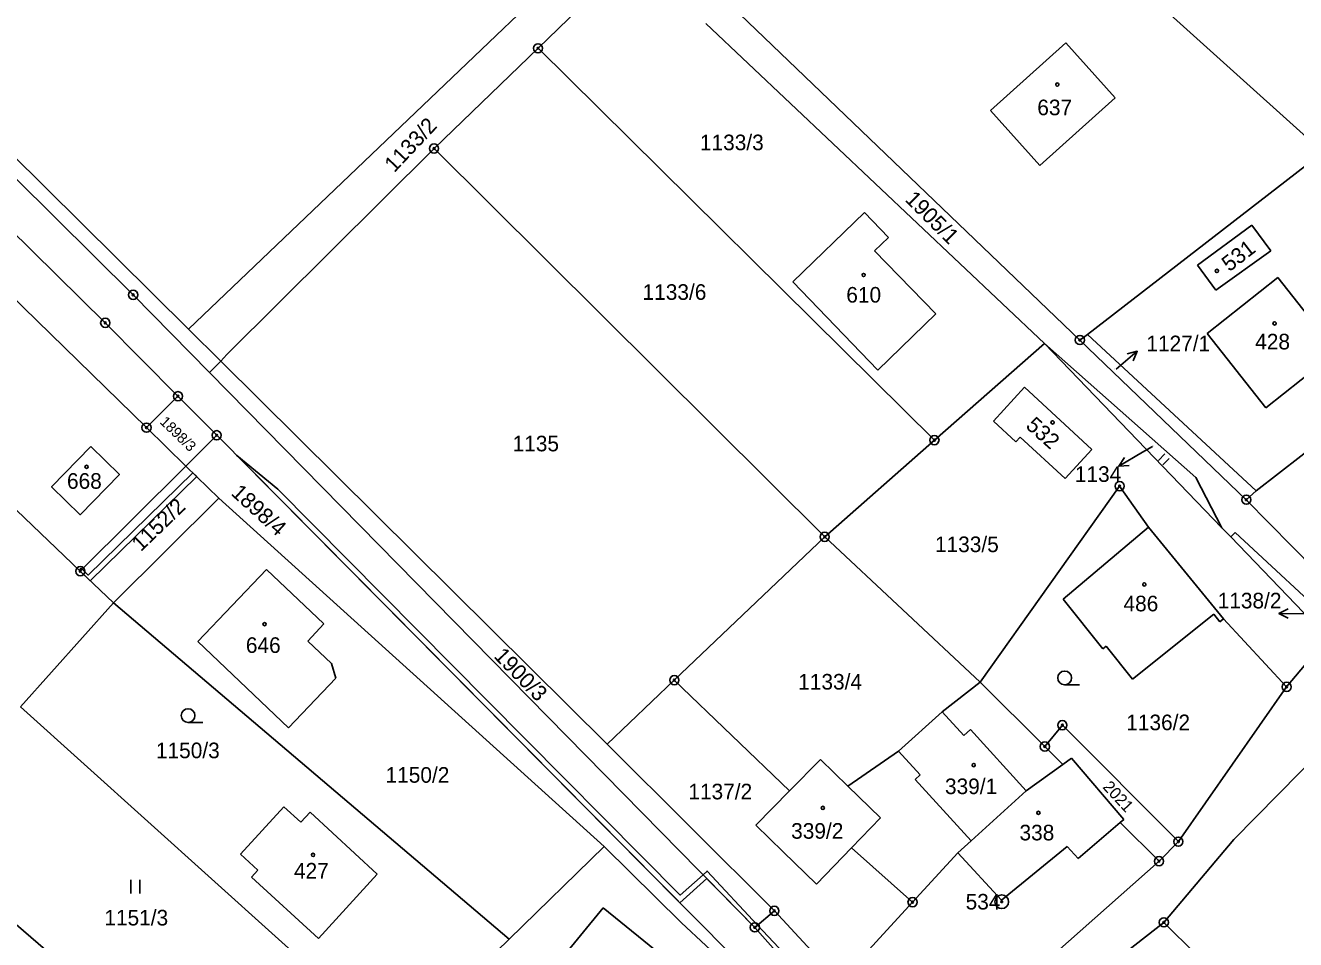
# Model space of a CAD drawing. Extents: x -445050 to -440454, y -1134563 to -1129741.
# Drawn here: x -441259.8 to -441121.4, y -1131805 to -1131705.4 of the extents above; entities that cross this region are included whole.
import ezdxf

# ---------------------------------------------------------------- set-up
doc = ezdxf.new("R2010")
doc.units = 0
for name, color, linetype in [('Vrstva 1', 7, 'Continuous'), ('Vrstva 16', 7, 'Continuous'), ('Vrstva 17', 7, 'Continuous'), ('Vrstva 18', 7, 'Continuous'), ('Vrstva 19', 7, 'Continuous'), ('Vrstva 24', 7, 'Continuous'), ('Vrstva 25', 7, 'Continuous'), ('Vrstva 3', 7, 'Continuous'), ('Vrstva 30', 7, 'Continuous'), ('Vrstva 37', 7, 'Continuous'), ('Vrstva 4', 7, 'Continuous')]:
    doc.layers.add(name, color=color, linetype=linetype)

msp = doc.modelspace()

# ---------------------------------------------------------------- linework, layer by layer
at = {"layer": 'Vrstva 1'}
for points in [[(-441248.08, -1131734.72), (-441303.6, -1131679.69)], [(-441300.44, -1131680.61), (-441242.06, -1131738.45)], [(-441118.41, -1131719.17), (-441155.71, -1131685.61)], [(-441195.77, -1131694.29), (-441242.06, -1131738.45)], [(-441293.38, -1131696.12), (-441251.12, -1131737.78)], [(-441203.97, -1131707.87), (-441192.94, -1131697.18)], [(-441182.85, -1131703.31), (-441144.93, -1131739.65)], [(-441291.37, -1131705.58), (-441246.63, -1131749.19)], [(-441185.69, -1131705.17), (-441148.77, -1131740.03)], [(-441154.66, -1131714.66), (-441146.47, -1131707.29)], [(-441146.47, -1131707.29), (-441141.09, -1131713.27)], [(-441215.3, -1131718.78), (-441203.97, -1131707.87)], [(-441203.97, -1131707.87), (-441160.78, -1131750.55)], [(-441141.09, -1131713.27), (-441149.3, -1131720.65)], [(-441149.3, -1131720.65), (-441154.66, -1131714.66)], [(-441303.31, -1131717.47), (-441253.84, -1131764.83)], [(-441237.86, -1131741.23), (-441215.3, -1131718.78)], [(-441215.3, -1131718.78), (-441172.73, -1131761.08)], [(-441144.1, -1131739.04), (-441118.41, -1131719.17)], [(-441176.19, -1131733.29), (-441168.39, -1131725.74)], [(-441168.39, -1131725.74), (-441165.79, -1131728.48)], [(-441132.12, -1131731.5), (-441126.19, -1131727.14)], [(-441126.19, -1131727.14), (-441124.14, -1131729.93)], [(-441165.79, -1131728.48), (-441167.3, -1131729.92)], [(-441167.3, -1131729.92), (-441160.63, -1131736.8)], [(-441124.14, -1131729.93), (-441130.13, -1131734.2)], [(-441130.13, -1131734.2), (-441132.12, -1131731.5)], [(-441166.95, -1131742.94), (-441176.19, -1131733.29)], [(-441131.06, -1131738.93), (-441123.36, -1131732.85)], [(-441123.36, -1131732.85), (-441116.97, -1131740.95)], [(-441239.76, -1131743.19), (-441248.08, -1131734.72)], [(-441251.12, -1131737.78), (-441243.2, -1131745.77)], [(-441160.63, -1131736.8), (-441166.95, -1131742.94)], [(-441242.06, -1131738.45), (-441238.54, -1131741.94)], [(-441144.93, -1131739.65), (-441144.1, -1131739.04)], [(-441144.1, -1131739.04), (-441125.74, -1131756.07)], [(-441124.67, -1131747.03), (-441131.06, -1131738.93)], [(-441148.77, -1131740.03), (-441160.78, -1131750.55)], [(-441148.77, -1131740.03), (-441129.45, -1131760.09)], [(-441132.31, -1131754.62), (-441148.77, -1131740.03)], [(-441126.8, -1131757.04), (-441144.93, -1131739.65)], [(-441238.54, -1131741.94), (-441239.76, -1131743.19)], [(-441237.86, -1131741.23), (-441238.54, -1131741.94)], [(-441196.43, -1131783.67), (-441238.54, -1131741.94)], [(-441116.97, -1131740.95), (-441124.67, -1131747.03)], [(-441180.35, -1131803.63), (-441239.76, -1131743.19)], [(-441246.63, -1131749.19), (-441243.2, -1131745.77)], [(-441243.2, -1131745.77), (-441238.98, -1131750.02)], [(-441154.36, -1131748.47), (-441150.98, -1131744.79)], [(-441150.98, -1131744.79), (-441143.62, -1131751.56)], [(-441151.9, -1131750.74), (-441154.36, -1131748.47)], [(-441246.63, -1131749.19), (-441242.34, -1131753.37)], [(-441238.98, -1131750.02), (-441242.34, -1131753.37)], [(-441238.98, -1131750.02), (-441183.06, -1131806.44)], [(-441151.43, -1131750.22), (-441151.9, -1131750.74)], [(-441146.53, -1131754.72), (-441151.43, -1131750.22)], [(-441252.7, -1131751.23), (-441249.58, -1131754.28), (-441253.85, -1131758.68), (-441256.97, -1131755.65), (-441252.7, -1131751.23)], [(-441160.78, -1131750.55), (-441172.73, -1131761.08)], [(-441143.62, -1131751.56), (-441146.53, -1131754.72)], [(-441125.74, -1131756.07), (-441118.44, -1131750.4)], [(-441242.34, -1131753.37), (-441253.84, -1131764.83)], [(-441242.34, -1131753.37), (-441238.75, -1131756.86)], [(-441155.78, -1131776.92), (-441140.6, -1131755.56)], [(-441140.6, -1131755.56), (-441137.45, -1131760.03)], [(-441129.45, -1131760.09), (-441132.31, -1131754.62)], [(-441250.23, -1131768.29), (-441238.75, -1131756.86)], [(-441196.77, -1131794.81), (-441238.75, -1131756.86)], [(-441125.74, -1131756.07), (-441126.8, -1131757.04)], [(-441114.29, -1131769.75), (-441126.8, -1131757.04)], [(-441172.73, -1131761.08), (-441189.12, -1131776.7)], [(-441172.73, -1131761.08), (-441155.78, -1131776.92)], [(-441146.77, -1131767.86), (-441137.45, -1131760.03)], [(-441137.45, -1131760.03), (-441129.28, -1131770.02)], [(-441129.45, -1131760.09), (-441128.49, -1131761.09)], [(-441128, -1131760.62), (-441128.49, -1131761.09)], [(-441128.49, -1131761.09), (-441117.9, -1131772.08)], [(-441116.58, -1131771.23), (-441128, -1131760.62)], [(-441253.84, -1131764.83), (-441250.23, -1131768.29)], [(-441241.03, -1131772.47), (-441233.57, -1131764.64)], [(-441233.57, -1131764.64), (-441227.29, -1131770.55)], [(-441142.42, -1131773.28), (-441146.77, -1131767.86)], [(-441260.37, -1131779.61), (-441250.23, -1131768.29)], [(-441250.23, -1131768.29), (-441207.13, -1131804.92)], [(-441130.34, -1131769.5), (-441139.2, -1131776.59)], [(-441129.67, -1131770.33), (-441130.34, -1131769.5)], [(-441227.29, -1131770.55), (-441229.04, -1131772.45)], [(-441129.28, -1131770.02), (-441129.67, -1131770.33)], [(-441129.28, -1131770.02), (-441122.41, -1131777.43)], [(-441122.41, -1131777.43), (-441117.9, -1131772.08)], [(-441231.16, -1131781.88), (-441241.03, -1131772.47)], [(-441229.04, -1131772.45), (-441226.48, -1131774.89)], [(-441142.07, -1131773), (-441142.42, -1131773.28)], [(-441139.2, -1131776.59), (-441142.07, -1131773)], [(-441226.48, -1131774.89), (-441226.01, -1131776.47)], [(-441226.01, -1131776.47), (-441231.16, -1131781.88)], [(-441189.12, -1131776.7), (-441196.43, -1131783.67)], [(-441189.12, -1131776.7), (-441176.58, -1131788.75)], [(-441159.94, -1131780.13), (-441155.78, -1131776.92)], [(-441155.78, -1131776.92), (-441148.75, -1131783.93)], [(-441134.2, -1131794.29), (-441122.41, -1131777.43)], [(-441260.37, -1131779.61), (-441218.75, -1131817.06)], [(-441164.68, -1131784.43), (-441159.94, -1131780.13)], [(-441128.15, -1131794.05), (-441113.67, -1131779.35)], [(-441146.84, -1131781.6), (-441148.75, -1131783.93)], [(-441146.84, -1131781.6), (-441134.2, -1131794.29)], [(-441196.43, -1131783.67), (-441178.22, -1131801.82)], [(-441170.23, -1131788.23), (-441164.68, -1131784.43)], [(-441148.75, -1131783.93), (-441146.8, -1131785.87)], [(-441173.21, -1131785.33), (-441176.58, -1131788.75)], [(-441173.21, -1131785.33), (-441170.23, -1131788.23)], [(-441150.77, -1131788.77), (-441146.8, -1131785.87)], [(-441146.8, -1131785.87), (-441145.85, -1131785.18)], [(-441145.85, -1131785.18), (-441140.15, -1131791.87)], [(-441176.58, -1131788.75), (-441180.25, -1131792.48)], [(-441170.23, -1131788.23), (-441166.65, -1131791.68)], [(-441156.78, -1131794.21), (-441150.77, -1131788.77)], [(-441236.37, -1131795.66), (-441231.65, -1131790.49)], [(-441231.65, -1131790.49), (-441229.8, -1131792.18)], [(-441229.8, -1131792.18), (-441228.79, -1131791.07)], [(-441228.79, -1131791.07), (-441221.48, -1131797.82)], [(-441166.65, -1131791.68), (-441169.81, -1131794.95)], [(-441180.25, -1131792.48), (-441177.25, -1131795.39)], [(-441145.13, -1131796.11), (-441140.54, -1131792.21)], [(-441140.54, -1131792.21), (-441140.15, -1131791.87)], [(-441140.54, -1131792.21), (-441136.31, -1131796.42)], [(-441156.78, -1131794.21), (-441158.22, -1131795.49)], [(-441134.2, -1131794.29), (-441136.31, -1131796.42)], [(-441135.78, -1131803.08), (-441128.15, -1131794.05)], [(-441234.49, -1131797.38), (-441236.37, -1131795.66)], [(-441207.13, -1131804.92), (-441196.77, -1131794.81)], [(-441196.77, -1131794.81), (-441188.32, -1131803.14)], [(-441177.25, -1131795.39), (-441173.64, -1131798.92)], [(-441169.81, -1131794.95), (-441173.64, -1131798.92)], [(-441163.16, -1131800.88), (-441169.81, -1131794.95)], [(-441158.22, -1131795.49), (-441163.16, -1131800.88)], [(-441153.47, -1131800.68), (-441158.22, -1131795.49)], [(-441146.32, -1131794.82), (-441153.47, -1131800.68)], [(-441145.13, -1131796.11), (-441146.32, -1131794.82)], [(-441136.31, -1131796.42), (-441149.04, -1131807.69)], [(-441235.2, -1131798.15), (-441234.49, -1131797.38)], [(-441227.89, -1131804.83), (-441235.2, -1131798.15)], [(-441221.48, -1131797.82), (-441227.89, -1131804.83)], [(-441163.16, -1131800.88), (-441171.09, -1131809.52)], [(-441240.67, -1131820.7), (-441261.88, -1131802.41)], [(-441201.47, -1131807.12), (-441196.88, -1131801.48)], [(-441196.88, -1131801.48), (-441189.94, -1131807.12)], [(-441178.22, -1131801.82), (-441180.35, -1131803.63)], [(-441171.09, -1131809.52), (-441178.22, -1131801.82)], [(-441188.32, -1131803.14), (-441183.04, -1131808.08)], [(-441135.78, -1131803.08), (-441151.43, -1131815.34)], [(-441135.78, -1131803.08), (-441132.25, -1131806.58)], [(-441209.91, -1131807.62), (-441207.13, -1131804.92)]]:
    msp.add_lwpolyline(points, dxfattribs=at)
at = {"layer": 'Vrstva 16'}
for p, q in [((-441140.96, -1131742.83), (-441138.69, -1131740.87)), ((-441138.1, -1131751.88), (-441140.68, -1131753.4)), ((-441120.24, -1131769.48), (-441123.24, -1131769.42))]:
    msp.add_line(p, q, dxfattribs=at)
for points in [[(-441139.77, -1131741.14), (-441138.69, -1131740.87), (-441139.12, -1131741.9)], [(-441137.03, -1131751.25), (-441138.1, -1131751.88)], [(-441139.57, -1131753.33), (-441140.68, -1131753.4), (-441140.08, -1131752.46)], [(-441122.25, -1131769.94), (-441123.24, -1131769.42), (-441122.23, -1131768.94)]]:
    msp.add_lwpolyline(points, dxfattribs=at)
at = {"layer": 'Vrstva 24'}
for centre, radius in [((-441203.97, -1131707.87), 0.5), ((-441203.97, -1131707.87), 0.1), ((-441215.3, -1131718.78), 0.5), ((-441215.3, -1131718.78), 0.1), ((-441248.08, -1131734.72), 0.5), ((-441248.08, -1131734.72), 0.1), ((-441251.12, -1131737.78), 0.5), ((-441251.12, -1131737.78), 0.1), ((-441144.93, -1131739.65), 0.5), ((-441144.93, -1131739.65), 0.1), ((-441243.2, -1131745.77), 0.5), ((-441243.2, -1131745.77), 0.1), ((-441246.63, -1131749.19), 0.5), ((-441246.63, -1131749.19), 0.1), ((-441238.98, -1131750.02), 0.5), ((-441238.98, -1131750.02), 0.1), ((-441160.78, -1131750.55), 0.5), ((-441160.78, -1131750.55), 0.1), ((-441140.6, -1131755.56), 0.5), ((-441140.6, -1131755.56), 0.1), ((-441126.8, -1131757.04), 0.5), ((-441126.8, -1131757.04), 0.1), ((-441172.73, -1131761.08), 0.5), ((-441172.73, -1131761.08), 0.1), ((-441253.84, -1131764.83), 0.5), ((-441253.84, -1131764.83), 0.1), ((-441189.12, -1131776.7), 0.5), ((-441189.12, -1131776.7), 0.1), ((-441122.41, -1131777.43), 0.5), ((-441122.41, -1131777.43), 0.1), ((-441146.84, -1131781.6), 0.5), ((-441146.84, -1131781.6), 0.1), ((-441148.75, -1131783.93), 0.5), ((-441148.75, -1131783.93), 0.1), ((-441134.2, -1131794.29), 0.5), ((-441134.2, -1131794.29), 0.1), ((-441136.31, -1131796.42), 0.5), ((-441136.31, -1131796.42), 0.1), ((-441153.45, -1131800.83), 0.75), ((-441178.22, -1131801.82), 0.5), ((-441163.16, -1131800.88), 0.5), ((-441163.16, -1131800.88), 0.1), ((-441153.45, -1131800.83), 0.1), ((-441178.22, -1131801.82), 0.1), ((-441135.78, -1131803.08), 0.5), ((-441180.35, -1131803.63), 0.5), ((-441180.35, -1131803.63), 0.1), ((-441135.78, -1131803.08), 0.1)]:
    msp.add_circle(centre, radius, dxfattribs=at)
at = {"layer": 'Vrstva 25'}
for p, q in [((-441136.38, -1131752.77), (-441135.66, -1131752.06)), ((-441135.9, -1131753.25), (-441135.19, -1131752.54)), ((-441146.59, -1131777.2), (-441144.99, -1131777.2)), ((-441242.1, -1131781.31), (-441240.5, -1131781.31)), ((-441248.35, -1131799.93), (-441248.35, -1131798.43)), ((-441247.35, -1131799.93), (-441247.35, -1131798.43))]:
    msp.add_line(p, q, dxfattribs=at)
for centre, radius in [((-441147.39, -1131711.82), 0.175), ((-441130, -1131732.12), 0.175), ((-441168.49, -1131732.56), 0.175), ((-441123.72, -1131737.84), 0.175), ((-441147.91, -1131748.62), 0.175), ((-441253.16, -1131753.46), 0.175), ((-441137.91, -1131766.27), 0.175), ((-441233.76, -1131770.6), 0.175), ((-441146.59, -1131776.45), 0.75), ((-441242.1, -1131780.56), 0.75), ((-441156.5, -1131785.95), 0.175), ((-441172.94, -1131790.61), 0.175), ((-441149.45, -1131791.15), 0.175), ((-441228.48, -1131795.73), 0.175)]:
    msp.add_circle(centre, radius, dxfattribs=at)
at = {"layer": 'Vrstva 3'}
for points in [[(-441154.66, -1131714.66), (-441146.47, -1131707.29)], [(-441146.47, -1131707.29), (-441141.09, -1131713.27)], [(-441141.09, -1131713.27), (-441149.3, -1131720.65)], [(-441149.3, -1131720.65), (-441154.66, -1131714.66)], [(-441176.19, -1131733.29), (-441168.39, -1131725.74)], [(-441168.39, -1131725.74), (-441165.79, -1131728.48)], [(-441132.12, -1131731.5), (-441126.19, -1131727.14)], [(-441126.19, -1131727.14), (-441124.14, -1131729.93)], [(-441165.79, -1131728.48), (-441167.3, -1131729.92)], [(-441167.3, -1131729.92), (-441160.63, -1131736.8)], [(-441124.14, -1131729.93), (-441130.13, -1131734.2)], [(-441130.13, -1131734.2), (-441132.12, -1131731.5)], [(-441166.95, -1131742.94), (-441176.19, -1131733.29)], [(-441131.06, -1131738.93), (-441123.36, -1131732.85)], [(-441123.36, -1131732.85), (-441116.97, -1131740.95)], [(-441160.63, -1131736.8), (-441166.95, -1131742.94)], [(-441124.67, -1131747.03), (-441131.06, -1131738.93)], [(-441116.97, -1131740.95), (-441124.67, -1131747.03)], [(-441154.36, -1131748.47), (-441150.98, -1131744.79)], [(-441150.98, -1131744.79), (-441143.62, -1131751.56)], [(-441151.9, -1131750.74), (-441154.36, -1131748.47)], [(-441151.43, -1131750.22), (-441151.9, -1131750.74)], [(-441146.53, -1131754.72), (-441151.43, -1131750.22)], [(-441252.7, -1131751.23), (-441249.58, -1131754.28), (-441253.85, -1131758.68), (-441256.97, -1131755.65), (-441252.7, -1131751.23)], [(-441143.62, -1131751.56), (-441146.53, -1131754.72)], [(-441146.77, -1131767.86), (-441137.45, -1131760.03)], [(-441137.45, -1131760.03), (-441129.28, -1131770.02)], [(-441241.03, -1131772.47), (-441233.57, -1131764.64)], [(-441233.57, -1131764.64), (-441227.29, -1131770.55)], [(-441142.42, -1131773.28), (-441146.77, -1131767.86)], [(-441130.34, -1131769.5), (-441139.2, -1131776.59)], [(-441129.67, -1131770.33), (-441130.34, -1131769.5)], [(-441227.29, -1131770.55), (-441229.04, -1131772.45)], [(-441129.28, -1131770.02), (-441129.67, -1131770.33)], [(-441231.16, -1131781.88), (-441241.03, -1131772.47)], [(-441229.04, -1131772.45), (-441226.48, -1131774.89)], [(-441142.07, -1131773), (-441142.42, -1131773.28)], [(-441139.2, -1131776.59), (-441142.07, -1131773)], [(-441226.48, -1131774.89), (-441226.01, -1131776.47)], [(-441226.01, -1131776.47), (-441231.16, -1131781.88)], [(-441164.68, -1131784.43), (-441159.94, -1131780.13)], [(-441159.94, -1131780.13), (-441157.59, -1131782.72)], [(-441157.59, -1131782.72), (-441156.85, -1131782.06)], [(-441156.85, -1131782.06), (-441150.77, -1131788.77)], [(-441162.34, -1131787.02), (-441164.68, -1131784.43)], [(-441173.21, -1131785.33), (-441176.58, -1131788.75)], [(-441173.21, -1131785.33), (-441170.23, -1131788.23)], [(-441150.77, -1131788.77), (-441146.8, -1131785.87)], [(-441146.8, -1131785.87), (-441145.85, -1131785.18)], [(-441145.85, -1131785.18), (-441140.15, -1131791.87)], [(-441162.86, -1131787.51), (-441162.34, -1131787.02)], [(-441156.78, -1131794.21), (-441162.86, -1131787.51)], [(-441176.58, -1131788.75), (-441180.25, -1131792.48)], [(-441170.23, -1131788.23), (-441166.65, -1131791.68)], [(-441156.78, -1131794.21), (-441150.77, -1131788.77)], [(-441156.78, -1131794.21), (-441150.77, -1131788.77)], [(-441236.37, -1131795.66), (-441231.65, -1131790.49)], [(-441231.65, -1131790.49), (-441229.8, -1131792.18)], [(-441229.8, -1131792.18), (-441228.79, -1131791.07)], [(-441228.79, -1131791.07), (-441221.48, -1131797.82)], [(-441166.65, -1131791.68), (-441169.81, -1131794.95)], [(-441180.25, -1131792.48), (-441177.25, -1131795.39)], [(-441145.13, -1131796.11), (-441140.54, -1131792.21)], [(-441140.54, -1131792.21), (-441140.15, -1131791.87)], [(-441156.78, -1131794.21), (-441158.22, -1131795.49)], [(-441234.49, -1131797.38), (-441236.37, -1131795.66)], [(-441177.25, -1131795.39), (-441173.64, -1131798.92)], [(-441169.81, -1131794.95), (-441173.64, -1131798.92)], [(-441153.47, -1131800.68), (-441158.22, -1131795.49)], [(-441146.32, -1131794.82), (-441153.47, -1131800.68)], [(-441145.13, -1131796.11), (-441146.32, -1131794.82)], [(-441235.2, -1131798.15), (-441234.49, -1131797.38)], [(-441227.89, -1131804.83), (-441235.2, -1131798.15)], [(-441221.48, -1131797.82), (-441227.89, -1131804.83)], [(-441201.47, -1131807.12), (-441196.88, -1131801.48)], [(-441196.88, -1131801.48), (-441189.94, -1131807.12)]]:
    msp.add_lwpolyline(points, dxfattribs=at)
at = {"layer": 'Vrstva 30'}
for points in [[(-441232.73, -1131756.33), (-441236.79, -1131752.23), (-441232.31, -1131755.88)], [(-441252.75, -1131765.87), (-441253.84, -1131764.83), (-441253.63, -1131764.62), (-441252.98, -1131765.25), (-441241.58, -1131754.1), (-441241.15, -1131754.52), (-441252.75, -1131765.87)], [(-441209.51, -1131778.9), (-441188.47, -1131800.11), (-441185.99, -1131797.9), (-441185.56, -1131798.32), (-441188.51, -1131800.95), (-441232.73, -1131756.33)], [(-441232.31, -1131755.88), (-441209.51, -1131778.9)], [(-441253.94, -1131764.73), (-441253.74, -1131764.51), (-441253.63, -1131764.62), (-441253.84, -1131764.83), (-441253.94, -1131764.73)], [(-441185.99, -1131797.9), (-441185.54, -1131797.5), (-441180.05, -1131803.38), (-441180.35, -1131803.63), (-441185.56, -1131798.32), (-441185.99, -1131797.9)], [(-441175.25, -1131809.39), (-441180.35, -1131803.63), (-441180.05, -1131803.38), (-441174.87, -1131808.92)]]:
    msp.add_lwpolyline(points, dxfattribs=at)
at = {"layer": 'Vrstva 37'}
for centre in [(-441147.39, -1131711.82), (-441130, -1131732.12), (-441168.49, -1131732.56), (-441123.72, -1131737.84), (-441147.91, -1131748.62), (-441253.16, -1131753.46), (-441137.91, -1131766.27), (-441233.76, -1131770.6), (-441156.5, -1131785.95), (-441172.94, -1131790.61), (-441149.45, -1131791.15), (-441228.48, -1131795.73)]:
    msp.add_circle(centre, 0.175, dxfattribs=at)
at = {"layer": 'Vrstva 4'}
for points in [[(-441159.94, -1131780.13), (-441157.59, -1131782.72)], [(-441157.59, -1131782.72), (-441156.85, -1131782.06)], [(-441156.85, -1131782.06), (-441150.77, -1131788.77)], [(-441162.34, -1131787.02), (-441164.68, -1131784.43)], [(-441162.86, -1131787.51), (-441162.34, -1131787.02)], [(-441156.78, -1131794.21), (-441162.86, -1131787.51)]]:
    msp.add_lwpolyline(points, dxfattribs=at)

# ---------------------------------------------------------------- texts
at = {"layer": 'Vrstva 16'}
for s, p in [('1127/1', (-441137.69, -1131740.87)), ('1134', (-441145.48, -1131755.1)), ('1138/2', (-441129.92, -1131768.88))]:
    msp.add_text(s, height=1.7, dxfattribs=at).set_placement(p)
at = {"layer": 'Vrstva 17'}
msp.add_text('534', height=1.7, dxfattribs=at).set_placement((-441157.38, -1131801.68))
at = {"layer": 'Vrstva 18'}
for s, height, rotation, p in [('1133/2', 1.7, 46.7361, (-441219.63, -1131721.48)), ('1905/1', 1.7, 315, (-441164.08, -1131724.43)), ('1898/3', 1.14, 315.8906, (-441245.25, -1131748.65)), ('1898/4', 1.7, 317.7742, (-441237.51, -1131756.45)), ('1152/2', 1.7, 43.9321, (-441247.25, -1131762.77)), ('1900/3', 1.7, 314.3403, (-441208.88, -1131774.16)), ('2021', 1.29, 312.8669, (-441142.52, -1131788.39))]:
    msp.add_text(s, height=height, rotation=rotation, dxfattribs=at).set_placement(p)
for s, height, p in [('1133/3', 1.7, (-441186.33, -1131718.97)), ('1133/6', 1.7, (-441192.58, -1131735.27)), ('1127/1', 0.1, (-441141.16, -1131742.85)), ('1135', 1.7, (-441206.74, -1131751.77)), ('1134', 0.1, (-441137.14, -1131751.25)), ('1133/5', 1.7, (-441160.72, -1131762.75)), ('1133/4', 1.7, (-441175.62, -1131777.72)), ('1136/2', 1.7, (-441139.88, -1131782.15)), ('1150/3', 1.7, (-441245.6, -1131785.2)), ('1150/2', 1.7, (-441220.58, -1131787.87)), ('1137/2', 1.7, (-441187.59, -1131789.68)), ('1151/3', 1.7, (-441251.22, -1131803.42))]:
    msp.add_text(s, height=height, dxfattribs=at).set_placement(p)
at = {"layer": 'Vrstva 19'}
for s, p in [('637', (-441149.57, -1131715.16)), ('610', (-441170.38, -1131735.57)), ('428', (-441125.83, -1131740.67)), ('668', (-441255.29, -1131755.85)), ('486', (-441140.18, -1131769.2)), ('646', (-441235.8, -1131773.73)), ('339/1', (-441159.63, -1131789.11)), ('339/2', (-441176.39, -1131793.97)), ('338', (-441151.51, -1131794.15)), ('427', (-441230.56, -1131798.31))]:
    msp.add_text(s, height=1.7, dxfattribs=at).set_placement(p)
for s, rotation, p in [('531', 37.5885, (-441128.65, -1131732.27)), ('532', 318.2337, (-441150.93, -1131749.13))]:
    msp.add_text(s, height=1.7, rotation=rotation, dxfattribs=at).set_placement(p)

doc.saveas('drawing.dxf')
